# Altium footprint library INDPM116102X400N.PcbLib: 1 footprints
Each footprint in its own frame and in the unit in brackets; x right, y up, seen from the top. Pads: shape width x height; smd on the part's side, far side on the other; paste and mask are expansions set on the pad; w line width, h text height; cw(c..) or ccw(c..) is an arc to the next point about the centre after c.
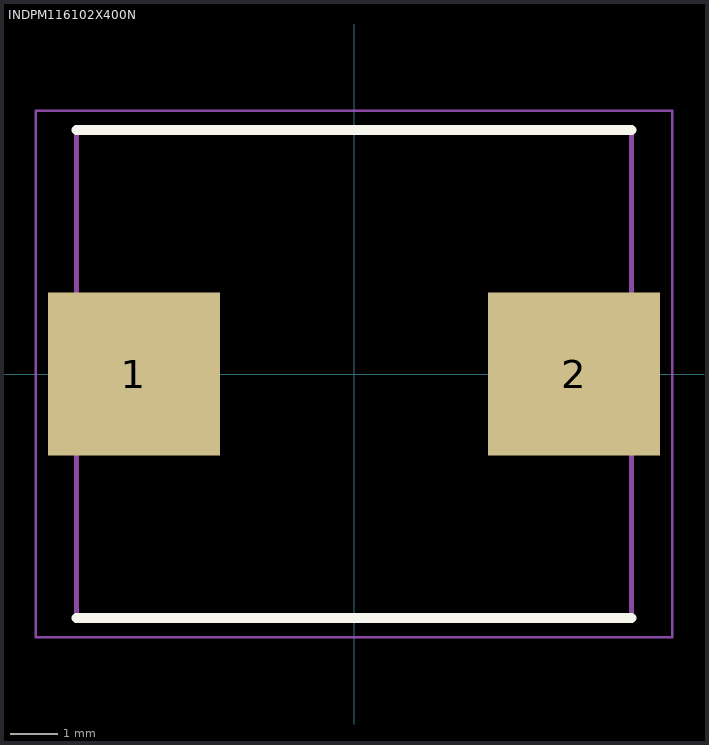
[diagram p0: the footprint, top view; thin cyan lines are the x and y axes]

## INDPM116102X400N [mm]
pads (2):
  rect 3.6x3.4 smd: 1(-4.6,0) 2(4.6,0)
Top Overlay:
  lines w0.2: -5.8,-5.1 5.8,-5.1 ; -5.8,5.1 5.8,5.1
Mechanical 15:
  lines w0.1: -5.8,-5.1 5.8,-5.1 5.8,5.1 -5.8,5.1 -5.8,-5.1
Mechanical 20:
  lines w0.05: -6.65,-5.5 6.65,-5.5 6.65,5.5 -6.65,5.5 -6.65,-5.5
